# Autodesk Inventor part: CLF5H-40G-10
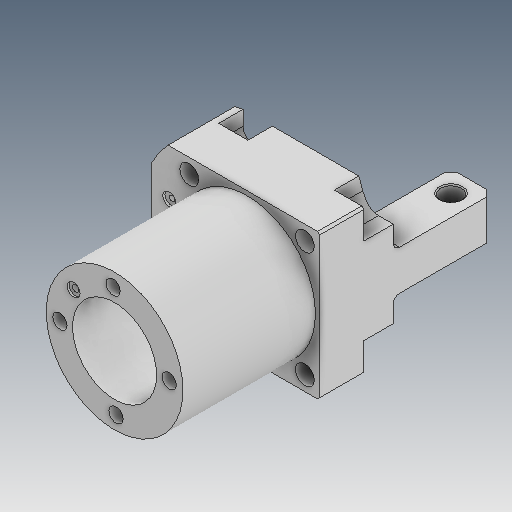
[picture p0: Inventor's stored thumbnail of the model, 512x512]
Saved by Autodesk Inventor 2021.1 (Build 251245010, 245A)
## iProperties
Created: 2013-04
Part Number: CLF5H-40G-10
Material: Ogólny
Document SubType Name: Modeling
Designer: user
Density: 1 g/cm^3
Appearance: Domyślna
Author: user
Revision Number: ÈÎºÎ
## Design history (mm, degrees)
feature "ÇÐ³ý-Ðý×ª1"
node "Bryła1"
